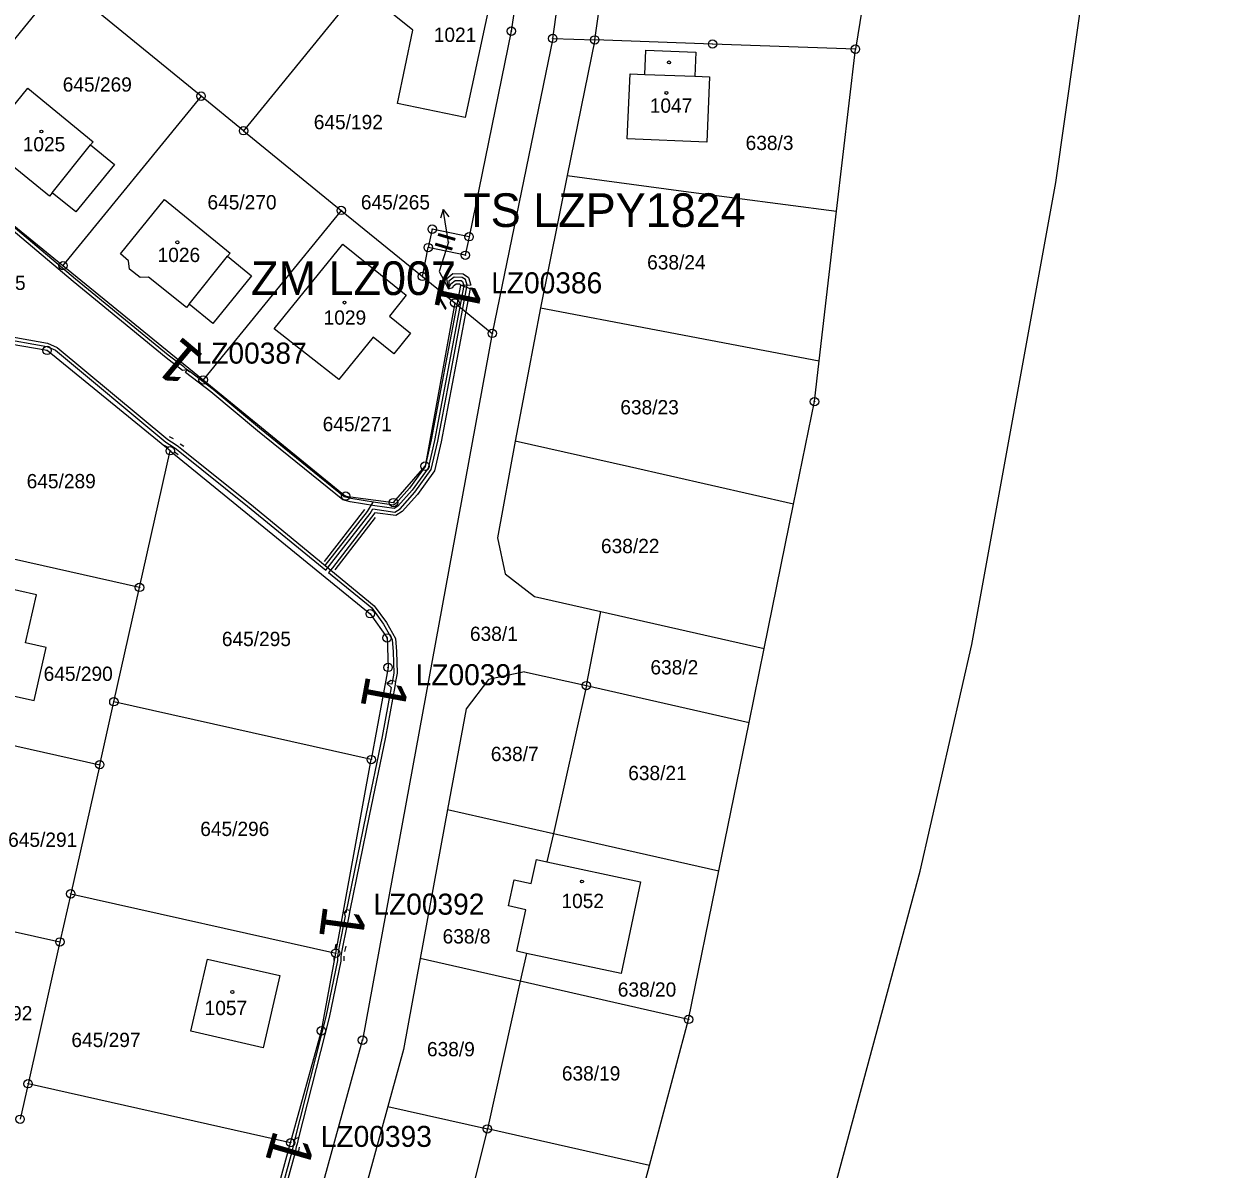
# Model space of a CAD drawing. Extents: x -738131 to -734179, y -1033447 to -1030078.
# Drawn here: x -735741.5 to -735599.7, y -1032945.2 to -1032809 of the extents above; entities that cross this region are included whole.
import ezdxf

# ---------------------------------------------------------------- set-up
doc = ezdxf.new("R2010")
doc.units = 0
for name, color, linetype in [('ftf_2010', 7, 'Continuous'), ('ftf_2060', 7, 'Continuous'), ('ftf_2140', 7, 'Continuous'), ('ftf_3010', 7, 'Continuous'), ('ftf_3010_ftf_3010_gtda_3015_gtda_3015_1', 7, 'Continuous'), ('ftf_3150', 7, 'Continuous'), ('ftf_3150_ftf_3150_gtda_3155_gtda_3155_1', 7, 'Continuous'), ('ftf_3160', 7, 'Continuous'), ('ftf_3160_ftf_3160_gtda_3165_gtda_3165_1', 7, 'Continuous'), ('ftf_3210', 7, 'Continuous'), ('Vrstva 1', 7, 'Continuous'), ('Vrstva 2', 7, 'Continuous'), ('Vrstva 4', 7, 'Continuous'), ('Vrstva 5', 7, 'Continuous'), ('Vrstva 7', 7, 'Continuous'), ('Vrstva 8', 7, 'Continuous')]:
    doc.layers.add(name, color=color, linetype=linetype)

msp = doc.modelspace()

# ---------------------------------------------------------------- linework, layer by layer
at = {"layer": 'ftf_2010'}
for points in [[(-735722.08, -1032850.15), (-735722.62, -1032850.2), (-735724.58, -1032848.7), (-735735.63, -1032839.65), (-735744.85, -1032831.9), (-735747.1, -1032829.96), (-735746.97, -1032829.81)], [(-735744.57, -1032846.33), (-735738.79, -1032847.35), (-735737.76, -1032847.81), (-735724.61, -1032858.75), (-735723.76, -1032859.29), (-735723.37, -1032859.57), (-735722.94, -1032859.87), (-735714.9, -1032866.34), (-735705.59, -1032873.97), (-735700.33, -1032867.22), (-735700, -1032866.68), (-735697.38, -1032867.04), (-735696.77, -1032866.66), (-735695.9, -1032865.68), (-735695.02, -1032864.7), (-735693.06, -1032861.98), (-735692.28, -1032858.62), (-735690.53, -1032849.43), (-735688.78, -1032840.08), (-735688.99, -1032839.39), (-735689.37, -1032839.14), (-735690.35, -1032839.1), (-735690.97, -1032839.59), (-735691.03, -1032840.5)], [(-735691.03, -1032840.5), (-735691.22, -1032839.28), (-735690.49, -1032838.69), (-735689.25, -1032838.74), (-735688.64, -1032839.14), (-735688.37, -1032840.06), (-735689.19, -1032840.1), (-735689.53, -1032840.07)], [(-735691.03, -1032840.5), (-735690.72, -1032839.9), (-735690.22, -1032839.5), (-735689.5, -1032839.53), (-735689.33, -1032839.65), (-735689.19, -1032840.1), (-735690.92, -1032849.35), (-735692.67, -1032858.54), (-735693.43, -1032861.81), (-735695.34, -1032864.45), (-735697.03, -1032866.35), (-735697.47, -1032866.62), (-735699.77, -1032866.31), (-735702.7, -1032865.83), (-735703.58, -1032865.59), (-735713.72, -1032857.4), (-735719.26, -1032852.77), (-735722.3, -1032850.44), (-735722.08, -1032850.15)], [(-735689.53, -1032840.07), (-735688.44, -1032840.45), (-735690.14, -1032849.5), (-735691.89, -1032858.71), (-735692.68, -1032862.15), (-735694.71, -1032864.95), (-735696.51, -1032866.97), (-735697.29, -1032867.45), (-735699.75, -1032867.12), (-735704.8, -1032873.66), (-735705.27, -1032874.24), (-735700.14, -1032878.45), (-735698.72, -1032880.38), (-735697.71, -1032882.2), (-735697.58, -1032883.66), (-735697.52, -1032886.18), (-735697.76, -1032887.52), (-735698.33, -1032887.41)], [(-735698.33, -1032887.41), (-735697.84, -1032887.91), (-735698.91, -1032893.74), (-735700.84, -1032903.07), (-735703.2, -1032914.71), (-735703.4, -1032914.67)], [(-735703.4, -1032914.67), (-735703.28, -1032915.1), (-735703.96, -1032918.49), (-735704.1, -1032919.12), (-735704.22, -1032919.85), (-735704.22, -1032920.38), (-735705.58, -1032927.06), (-735709.33, -1032941.73), (-735709.43, -1032941.7)], [(-735709.43, -1032941.7), (-735709.42, -1032942.11), (-735709.5, -1032942.41), (-735709.64, -1032943.11), (-735715.59, -1032964.82), (-735717.09, -1032970.28), (-735717.3, -1032970.22)]]:
    msp.add_lwpolyline(points, dxfattribs=at)
at = {"layer": 'ftf_2060'}
msp.add_lwpolyline([(-735691.03, -1032834.95), (-735692.12, -1032838.43), (-735691.03, -1032840.5)], dxfattribs=at)
at = {"layer": 'ftf_2140'}
for points in [[(-735722.08, -1032850.15), (-735722.5, -1032849.79), (-735724.33, -1032848.38), (-735735.38, -1032839.34), (-735744.59, -1032831.6), (-735746.53, -1032829.92), (-735746.97, -1032829.81)], [(-735691.03, -1032840.5), (-735690.49, -1032840.33), (-735690.4, -1032840.16), (-735690.09, -1032839.91), (-735689.66, -1032839.93), (-735689.6, -1032840.12), (-735691.32, -1032849.28), (-735693.06, -1032858.46), (-735693.8, -1032861.64), (-735695.65, -1032864.2), (-735697.29, -1032866.04), (-735697.56, -1032866.21), (-735699.71, -1032865.91), (-735702.62, -1032865.44), (-735703.4, -1032865.23), (-735713.47, -1032857.09), (-735719.01, -1032852.46), (-735721.74, -1032850.37), (-735722.08, -1032850.15), (-735721.76, -1032850.39)], [(-735689.6, -1032840.12), (-735689.53, -1032840.07)], [(-735762.04, -1032872.47), (-735762.13, -1032872.86), (-735761.74, -1032871.84), (-735761.7, -1032871.39), (-735761.65, -1032870.28), (-735761.42, -1032869.76), (-735756.82, -1032848.83), (-735756.03, -1032848.63), (-735749.27, -1032850.39), (-735748.74, -1032850.35), (-735744.72, -1032845.9), (-735738.68, -1032846.96), (-735737.55, -1032847.47), (-735724.37, -1032858.43), (-735723.53, -1032858.96), (-735723.13, -1032859.25), (-735722.7, -1032859.55), (-735714.65, -1032866.02), (-735705.66, -1032873.4), (-735700.66, -1032866.99), (-735699.97, -1032865.87)], [(-735705.66, -1032873.4), (-735699.85, -1032878.18), (-735698.38, -1032880.16), (-735697.32, -1032882.08), (-735697.18, -1032883.64), (-735697.12, -1032886.21), (-735697.3, -1032887.19)], [(-735697.3, -1032887.19), (-735697.4, -1032887.77), (-735698.52, -1032893.82), (-735700.45, -1032903.15), (-735702.73, -1032914.4)], [(-735697.3, -1032887.19), (-735697.86, -1032887.09), (-735698.33, -1032887.41)], [(-735702.73, -1032914.4), (-735702.86, -1032915.09), (-735703.57, -1032918.58), (-735703.71, -1032919.19), (-735703.82, -1032919.88), (-735703.82, -1032920.42), (-735705.2, -1032927.15), (-735708.84, -1032941.44)], [(-735702.73, -1032914.4), (-735703.12, -1032914.32), (-735703.4, -1032914.67)], [(-735708.84, -1032941.44), (-735709.02, -1032942.16), (-735709.11, -1032942.5), (-735709.25, -1032943.2), (-735715.21, -1032964.92), (-735716.6, -1032970)], [(-735709.43, -1032941.7), (-735708.94, -1032941.41), (-735708.84, -1032941.44)]]:
    msp.add_lwpolyline(points, dxfattribs=at)
at = {"layer": 'ftf_3210'}
for p, q in [((-735724.8, -1032859.1), (-735724.34, -1032859.36)), ((-735724.23, -1032858.05), (-735723.76, -1032858.31)), ((-735722.91, -1032858.92), (-735722.48, -1032859.22)), ((-735723.6, -1032859.9), (-735723.17, -1032860.2)), ((-735704.49, -1032919.03), (-735704.35, -1032918.41)), ((-735703.32, -1032919.29), (-735703.18, -1032918.67)), ((-735704.62, -1032920.38), (-735704.62, -1032919.85)), ((-735703.42, -1032920.39), (-735703.42, -1032919.85)), ((-735710.03, -1032943.03), (-735709.89, -1032942.33)), ((-735708.86, -1032943.27), (-735708.72, -1032942.57))]:
    msp.add_line(p, q, dxfattribs=at)
for points in [[(-735705.75, -1032872.92), (-735700.97, -1032866.73)], [(-735704.48, -1032873.9), (-735699.7, -1032867.71)]]:
    msp.add_lwpolyline(points, dxfattribs=at)
at = {"layer": 'Vrstva 1'}
for points in [[(-735618.81, -1032827.88), (-735599.73, -1032693.71)], [(-735678.61, -1032810.73), (-735671.11, -1032757.76)], [(-735693.81, -1032795.23), (-735715.38, -1032821.71)], [(-735673.62, -1032810.91), (-735671.64, -1032796.97)], [(-735640.26, -1032797.6), (-735642.62, -1032812.01)], [(-735737.09, -1032804.02), (-735753.52, -1032824.17)], [(-735685.85, -1032805.34), (-735689.03, -1032820.13)], [(-735682.74, -1032804.24), (-735683.54, -1032809.87)], [(-735720.43, -1032817.6), (-735732.44, -1032807.81)], [(-735695.26, -1032809.74), (-735698.47, -1032807.19)], [(-735697.07, -1032818.48), (-735695.26, -1032809.74)], [(-735683.54, -1032809.87), (-735688.56, -1032834.31)], [(-735678.61, -1032810.73), (-735685.81, -1032845.8)], [(-735678.61, -1032810.73), (-735673.62, -1032810.91)], [(-735673.62, -1032810.91), (-735676.89, -1032827.05)], [(-735659.61, -1032811.4), (-735673.62, -1032810.91)], [(-735667.66, -1032815.01), (-735667.55, -1032812.12), (-735661.62, -1032812.35), (-735661.73, -1032815.24)], [(-735642.62, -1032812.01), (-735659.61, -1032811.4)], [(-735644.86, -1032831.28), (-735642.62, -1032812.01)], [(-735661.73, -1032815.24), (-735659.96, -1032815.31), (-735660.28, -1032823.05), (-735669.75, -1032822.69), (-735669.41, -1032814.94)], [(-735669.41, -1032814.94), (-735667.66, -1032815.01)], [(-735746.3, -1032823.09), (-735741.05, -1032816.65)], [(-735741.05, -1032816.65), (-735733.27, -1032823.02)], [(-735720.43, -1032817.6), (-735736.85, -1032837.75)], [(-735715.38, -1032821.71), (-735720.43, -1032817.6)], [(-735689.03, -1032820.13), (-735697.07, -1032818.48)], [(-735715.38, -1032821.71), (-735703.76, -1032831.18)], [(-735733.27, -1032823.02), (-735733.58, -1032823.4)], [(-735733.58, -1032823.4), (-735730.73, -1032825.73)], [(-735753.52, -1032824.17), (-735736.85, -1032837.75)], [(-735738.46, -1032829.48), (-735742.98, -1032825.8)], [(-735730.73, -1032825.73), (-735735.33, -1032831.36)], [(-735676.89, -1032827.05), (-735680.08, -1032842.77)], [(-735676.89, -1032827.05), (-735663.05, -1032828.88)], [(-735628.79, -1032882.8), (-735618.81, -1032827.88)], [(-735738.15, -1032829.1), (-735738.46, -1032829.48)], [(-735735.33, -1032831.36), (-735738.15, -1032829.1)], [(-735663.05, -1032828.88), (-735644.86, -1032831.28)], [(-735730.01, -1032836.35), (-735724.78, -1032829.9)], [(-735724.78, -1032829.9), (-735716.97, -1032836.26)], [(-735703.76, -1032831.18), (-735720.18, -1032851.34)], [(-735703.76, -1032831.18), (-735694.12, -1032839.03)], [(-735646.93, -1032849.07), (-735644.86, -1032831.28)], [(-735692.94, -1032833.41), (-735693.42, -1032835.6)], [(-735688.56, -1032834.31), (-735692.94, -1032833.41)], [(-735688.56, -1032834.31), (-735689.01, -1032836.51)], [(-735729.05, -1032837.17), (-735730.01, -1032836.35)], [(-735716.97, -1032836.26), (-735717.28, -1032836.64)], [(-735711.75, -1032845.26), (-735703.59, -1032835.21)], [(-735703.59, -1032835.21), (-735696.03, -1032841.26)], [(-735694.12, -1032839.03), (-735693.42, -1032835.6)], [(-735689.01, -1032836.51), (-735693.42, -1032835.6)], [(-735736.85, -1032837.75), (-735720.18, -1032851.34)], [(-735728.93, -1032838.16), (-735729.05, -1032837.17)], [(-735717.28, -1032836.64), (-735714.42, -1032838.97)], [(-735727.66, -1032839.17), (-735728.93, -1032838.16)], [(-735726.67, -1032839.12), (-735727.66, -1032839.17)], [(-735722.16, -1032842.72), (-735726.67, -1032839.12)], [(-735714.42, -1032838.97), (-735719.03, -1032844.63)], [(-735694.12, -1032839.03), (-735690.26, -1032842.18)], [(-735696.03, -1032841.26), (-735698.04, -1032843.77)], [(-735690.26, -1032842.18), (-735693.79, -1032861.59)], [(-735690.26, -1032842.18), (-735685.81, -1032845.8)], [(-735721.84, -1032842.33), (-735722.16, -1032842.72)], [(-735719.03, -1032844.63), (-735721.84, -1032842.33)], [(-735680.08, -1032842.77), (-735683.07, -1032858.61)], [(-735680.08, -1032842.77), (-735666.3, -1032845.39)], [(-735698.04, -1032843.77), (-735695.52, -1032845.78)], [(-735704.05, -1032851.3), (-735711.75, -1032845.26)], [(-735699.96, -1032846.26), (-735704.05, -1032851.3)], [(-735685.81, -1032845.8), (-735701.24, -1032929.83)], [(-735697.5, -1032848.22), (-735699.96, -1032846.26)], [(-735695.52, -1032845.78), (-735697.5, -1032848.22)], [(-735666.3, -1032845.39), (-735646.93, -1032849.07)], [(-735738.74, -1032847.83), (-735744.57, -1032846.85)], [(-735724.1, -1032859.75), (-735738.74, -1032847.83)], [(-735647.49, -1032853.92), (-735646.93, -1032849.07)], [(-735720.18, -1032851.34), (-735703.24, -1032865.14)], [(-735649.97, -1032866.1), (-735647.49, -1032853.92)], [(-735683.07, -1032858.61), (-735685.18, -1032870.09)], [(-735669.5, -1032861.68), (-735683.07, -1032858.61)], [(-735727.75, -1032876), (-735724.1, -1032859.75)], [(-735724.1, -1032859.75), (-735700.31, -1032879.13)], [(-735697.55, -1032865.92), (-735693.79, -1032861.59)], [(-735649.97, -1032866.1), (-735669.5, -1032861.68)], [(-735703.24, -1032865.14), (-735697.55, -1032865.92)], [(-735653.47, -1032883.25), (-735649.97, -1032866.1)], [(-735727.75, -1032876), (-735752.63, -1032870.43)], [(-735685.18, -1032870.09), (-735684.27, -1032874.39)], [(-735684.27, -1032874.39), (-735680.79, -1032877.07)], [(-735740.01, -1032876.87), (-735746.35, -1032875.45)], [(-735730.8, -1032889.6), (-735727.75, -1032876)], [(-735741.29, -1032882.6), (-735740.01, -1032876.87)], [(-735680.79, -1032877.07), (-735672.88, -1032878.86)], [(-735674.62, -1032887.68), (-735672.88, -1032878.86)], [(-735672.88, -1032878.86), (-735653.47, -1032883.25)], [(-735700.31, -1032879.13), (-735698.31, -1032882.01)], [(-735738.85, -1032883.15), (-735741.29, -1032882.6)], [(-735740.27, -1032889.46), (-735738.85, -1032883.15)], [(-735698.31, -1032882.01), (-735698.19, -1032885.52)], [(-735655.26, -1032892.07), (-735653.47, -1032883.25)], [(-735634.93, -1032909.75), (-735628.79, -1032882.8)], [(-735698.19, -1032885.52), (-735700.2, -1032896.48)], [(-735681.96, -1032886.03), (-735686.27, -1032886.94)], [(-735681.96, -1032886.03), (-735674.62, -1032887.68)], [(-735751.22, -1032887.02), (-735740.27, -1032889.46)], [(-735686.27, -1032886.94), (-735688.92, -1032890.45)], [(-735674.62, -1032887.68), (-735678.54, -1032905.26)], [(-735674.62, -1032887.68), (-735655.26, -1032892.07)], [(-735732.48, -1032897.08), (-735730.8, -1032889.6)], [(-735700.2, -1032896.48), (-735730.8, -1032889.6)], [(-735757.35, -1032891.51), (-735732.48, -1032897.08)], [(-735688.92, -1032890.45), (-735691.12, -1032902.42)], [(-735658.86, -1032909.71), (-735655.26, -1032892.07)], [(-735732.48, -1032897.08), (-735735.93, -1032912.43)], [(-735704.42, -1032919.5), (-735700.2, -1032896.48)], [(-735691.12, -1032902.42), (-735694.37, -1032920.13)], [(-735691.12, -1032902.42), (-735678.54, -1032905.26)], [(-735678.54, -1032905.26), (-735679.3, -1032908.64)], [(-735678.54, -1032905.26), (-735658.86, -1032909.71)], [(-735681.18, -1032911.21), (-735680.56, -1032908.37)], [(-735680.56, -1032908.37), (-735679.3, -1032908.64)], [(-735679.3, -1032908.64), (-735668.17, -1032911)], [(-735662.46, -1032927.37), (-735658.86, -1032909.71)], [(-735649.28, -1032962.9), (-735634.93, -1032909.75)], [(-735683.87, -1032913.88), (-735683.21, -1032910.78)], [(-735683.21, -1032910.78), (-735681.18, -1032911.21)], [(-735668.17, -1032911), (-735670.49, -1032921.92)], [(-735762.07, -1032912.58), (-735737.21, -1032918.15)], [(-735735.93, -1032912.43), (-735737.21, -1032918.15)], [(-735735.93, -1032912.43), (-735704.42, -1032919.5)], [(-735681.81, -1032914.32), (-735683.87, -1032913.88)], [(-735682.87, -1032919.26), (-735681.81, -1032914.32)], [(-735737.21, -1032918.15), (-735741, -1032935.01)], [(-735713.04, -1032930.74), (-735721.63, -1032928.78), (-735719.67, -1032920.19), (-735711.07, -1032922.16), (-735713.04, -1032930.74)], [(-735706.12, -1032928.72), (-735704.42, -1032919.5)], [(-735694.37, -1032920.13), (-735696.36, -1032930.96)], [(-735682.47, -1032922.83), (-735694.37, -1032920.13)], [(-735681.73, -1032919.51), (-735682.87, -1032919.26)], [(-735681.73, -1032919.51), (-735682.47, -1032922.83)], [(-735670.49, -1032921.92), (-735681.73, -1032919.51)], [(-735682.47, -1032922.83), (-735686.39, -1032940.38)], [(-735662.46, -1032927.37), (-735682.47, -1032922.83)], [(-735667.12, -1032944.75), (-735662.46, -1032927.37)], [(-735720.05, -1032998.33), (-735701.24, -1032929.83)], [(-735709.78, -1032942.02), (-735706.12, -1032928.72)], [(-735696.36, -1032930.96), (-735698.21, -1032937.72)], [(-735741, -1032935.01), (-735741.95, -1032939.23)], [(-735709.78, -1032942.02), (-735741, -1032935.01)], [(-735698.21, -1032937.72), (-735702.99, -1032955.09)], [(-735698.21, -1032937.72), (-735686.39, -1032940.38)], [(-735686.39, -1032940.38), (-735690.79, -1032957.85)], [(-735667.12, -1032944.75), (-735686.39, -1032940.38)], [(-735716.06, -1032964.92), (-735709.78, -1032942.02)], [(-735671.79, -1032962.15), (-735667.12, -1032944.75)]]:
    msp.add_lwpolyline(points, dxfattribs=at)
at = {"layer": 'Vrstva 4'}
for points in [[(-735667.66, -1032815.01), (-735661.73, -1032815.24)], [(-735738.15, -1032829.1), (-735733.58, -1032823.4)], [(-735721.84, -1032842.33), (-735717.28, -1032836.64)]]:
    msp.add_lwpolyline(points, dxfattribs=at)
at = {"layer": 'Vrstva 5'}
for centre in [(-735664.79, -1032813.59), (-735665.1, -1032817.21), (-735739.42, -1032821.8), (-735723.25, -1032834.98), (-735703.38, -1032842.14), (-735675.14, -1032910.97), (-735716.71, -1032924.11)]:
    msp.add_circle(centre, 0.175, dxfattribs=at)
at = {"layer": 'Vrstva 7'}
for p, q in [((-735691.64, -1032831.06), (-735691.97, -1032832.12)), ((-735691.16, -1032834.02), (-735691.64, -1032831.06)), ((-735691.64, -1032831.06), (-735690.98, -1032831.96))]:
    msp.add_line(p, q, dxfattribs=at)
msp.add_lwpolyline([(-735691.01, -1032834.98), (-735691.16, -1032834.02)], dxfattribs=at)
at = {"layer": 'Vrstva 8'}
for centre, radius in [((-735683.54, -1032809.87), 0.5), ((-735683.54, -1032809.87), 0.0303), ((-735678.61, -1032810.73), 0.5), ((-735678.61, -1032810.73), 0.0303), ((-735673.62, -1032810.91), 0.5), ((-735673.62, -1032810.91), 0.0303), ((-735659.61, -1032811.4), 0.5), ((-735659.61, -1032811.4), 0.0303), ((-735642.62, -1032812.01), 0.5), ((-735642.62, -1032812.01), 0.0303), ((-735720.43, -1032817.6), 0.5), ((-735720.43, -1032817.6), 0.0303), ((-735715.38, -1032821.71), 0.5), ((-735715.38, -1032821.71), 0.0303), ((-735703.76, -1032831.18), 0.5), ((-735703.76, -1032831.18), 0.0303), ((-735692.94, -1032833.41), 0.5), ((-735692.94, -1032833.41), 0.0303), ((-735693.42, -1032835.6), 0.5), ((-735688.56, -1032834.31), 0.5), ((-735688.56, -1032834.31), 0.0303), ((-735693.42, -1032835.6), 0.0303), ((-735689.01, -1032836.51), 0.5), ((-735689.01, -1032836.51), 0.0303), ((-735736.85, -1032837.75), 0.5), ((-735736.85, -1032837.75), 0.0303), ((-735694.12, -1032839.03), 0.5), ((-735694.12, -1032839.03), 0.0303), ((-735690.26, -1032842.18), 0.5), ((-735690.26, -1032842.18), 0.0303), ((-735685.81, -1032845.8), 0.5), ((-735685.81, -1032845.8), 0.0303), ((-735738.74, -1032847.83), 0.5), ((-735738.74, -1032847.83), 0.0303), ((-735720.18, -1032851.34), 0.5), ((-735720.18, -1032851.34), 0.0303), ((-735647.49, -1032853.92), 0.5), ((-735647.49, -1032853.92), 0.0303), ((-735724.1, -1032859.75), 0.5), ((-735724.1, -1032859.75), 0.0303), ((-735693.79, -1032861.59), 0.5), ((-735693.79, -1032861.59), 0.0303), ((-735703.24, -1032865.14), 0.5), ((-735703.24, -1032865.14), 0.0303), ((-735697.55, -1032865.92), 0.5), ((-735697.55, -1032865.92), 0.0303), ((-735727.75, -1032876), 0.5), ((-735727.75, -1032876), 0.0303), ((-735700.31, -1032879.13), 0.5), ((-735700.31, -1032879.13), 0.0303), ((-735698.31, -1032882.01), 0.5), ((-735698.31, -1032882.01), 0.0303), ((-735698.19, -1032885.52), 0.5), ((-735698.19, -1032885.52), 0.0303), ((-735674.62, -1032887.68), 0.5), ((-735674.62, -1032887.68), 0.0303), ((-735730.8, -1032889.6), 0.5), ((-735730.8, -1032889.6), 0.0303), ((-735700.2, -1032896.48), 0.5), ((-735732.48, -1032897.08), 0.5), ((-735732.48, -1032897.08), 0.0303), ((-735700.2, -1032896.48), 0.0303), ((-735735.93, -1032912.43), 0.5), ((-735735.93, -1032912.43), 0.0303), ((-735737.21, -1032918.15), 0.5), ((-735737.21, -1032918.15), 0.0303), ((-735704.42, -1032919.5), 0.5), ((-735704.42, -1032919.5), 0.0303), ((-735662.46, -1032927.37), 0.5), ((-735706.12, -1032928.72), 0.5), ((-735706.12, -1032928.72), 0.0303), ((-735662.46, -1032927.37), 0.0303), ((-735701.24, -1032929.83), 0.5), ((-735701.24, -1032929.83), 0.0303), ((-735741, -1032935.01), 0.5), ((-735741, -1032935.01), 0.0303), ((-735741.95, -1032939.23), 0.5), ((-735686.39, -1032940.38), 0.5), ((-735686.39, -1032940.38), 0.0303), ((-735709.78, -1032942.02), 0.5), ((-735709.78, -1032942.02), 0.0303)]:
    msp.add_circle(centre, radius, dxfattribs=at)

# ---------------------------------------------------------------- texts
at = {"layer": 'ftf_3010'}
for rotation, p in [(258.5148, (-735691.95, -1032838.92)), (139.9835, (-735719.91, -1032848.57)), (259.4656, (-735700.77, -1032886.3)), (262.3825, (-735705.89, -1032913.68)), (253.8532, (-735711.75, -1032940.35))]:
    msp.add_text('1', height=5.2, rotation=rotation, dxfattribs=at).set_placement(p)
at = {"layer": 'ftf_3010_ftf_3010_gtda_3015_gtda_3015_1'}
for s, p in [('LZ00386', (-735685.93, -1032841.04)), ('LZ00387', (-735721.08, -1032849.4)), ('LZ00391', (-735694.91, -1032887.63)), ('LZ00392', (-735699.94, -1032914.91)), ('LZ00393', (-735706.19, -1032942.52))]:
    msp.add_text(s, height=2.5, dxfattribs=at).set_placement(p)
at = {"layer": 'ftf_3150'}
msp.add_text('>', height=2.7, rotation=144.7924, dxfattribs=at).set_placement((-735689.93, -1032841.28))
at = {"layer": 'ftf_3150_ftf_3150_gtda_3155_gtda_3155_1'}
msp.add_text('ZM LZ007', height=4, dxfattribs=at).set_placement((-735714.49, -1032841.24))
at = {"layer": 'ftf_3160'}
msp.add_text('=', height=3.3, rotation=343.5755, dxfattribs=at).set_placement((-735693.08, -1032836.06))
at = {"layer": 'ftf_3160_ftf_3160_gtda_3165_gtda_3165_1'}
msp.add_text('TS LZPY1824', height=4, dxfattribs=at).set_placement((-735689.26, -1032833.15))
at = {"layer": 'Vrstva 2'}
for s, height, p in [('1021', 1.7, (-735692.76, -1032811.15)), ('645/269', 1.7, (-735736.88, -1032817.06)), ('1047', 1.7, (-735667.08, -1032819.57)), ('645/192', 1.7, (-735707.03, -1032821.53)), ('638/3', 1.7, (-735655.68, -1032824)), ('1025', 1.7, (-735741.64, -1032824.16)), ('645/270', 1.7, (-735719.67, -1032831.06)), ('645/265', 0.1, (-735691.27, -1032834.98)), ('1026', 1.7, (-735725.6, -1032837.32)), ('638/24', 1.7, (-735667.39, -1032838.2)), ('645/305', 1.7, (-735749.51, -1032840.64)), ('1029', 1.7, (-735705.86, -1032844.77)), ('638/23', 1.7, (-735670.58, -1032855.43)), ('645/271', 1.7, (-735705.97, -1032857.43)), ('645/289', 1.7, (-735741.17, -1032864.22)), ('638/22', 1.7, (-735672.88, -1032871.93)), ('645/295', 1.7, (-735717.96, -1032882.98)), ('638/1', 1.7, (-735688.46, -1032882.37)), ('638/2', 1.7, (-735667, -1032886.35)), ('645/290', 1.7, (-735739.15, -1032887.12)), ('638/7', 1.7, (-735685.98, -1032896.65)), ('638/21', 1.7, (-735669.64, -1032898.92)), ('645/296', 1.7, (-735720.53, -1032905.56)), ('645/291', 1.7, (-735743.37, -1032906.85)), ('1052', 1.7, (-735677.58, -1032914.13)), ('638/8', 1.7, (-735691.71, -1032918.34)), ('638/20', 1.7, (-735670.88, -1032924.66)), ('645/292', 1.7, (-735748.71, -1032927.48)), ('1057', 1.7, (-735720.01, -1032926.85)), ('1057', 1.7, (-735720.01, -1032926.85)), ('645/297', 1.7, (-735735.85, -1032930.65)), ('645/297', 1.7, (-735735.85, -1032930.65)), ('638/9', 1.7, (-735693.57, -1032931.75)), ('638/19', 1.7, (-735677.53, -1032934.63))]:
    msp.add_text(s, height=height, dxfattribs=at).set_placement(p)
at = {"layer": 'Vrstva 7'}
msp.add_text('645/265', height=1.7, dxfattribs=at).set_placement((-735701.43, -1032831.06))

doc.saveas('drawing.dxf')
